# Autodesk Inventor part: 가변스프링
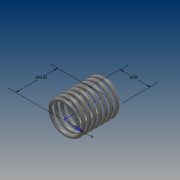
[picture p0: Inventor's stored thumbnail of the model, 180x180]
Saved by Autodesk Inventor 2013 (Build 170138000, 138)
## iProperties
Created: 2015-01
Part Number: 가변스프링
Material: 강철, 탄소
Document SubType Name: Modeling
Designer: Administrator
Density: 7.87 g/cm^3
Mass: 80.1301 g
Surface Area: 103.217 cm^2
Volume: 10.1817 cm^3
Author: Administrator
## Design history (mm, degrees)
sketch "스케치1"
  geometry: L1 (0, 0)-(17.5, 0); L2 (17.5, 0)-(17.5, 48.5); L3 (17.5, 48.5)-(0, 48.5); L4 (0, 48.5)-(0, 0); C1 r 2 at (17.5, 0)
  constraints: 8 end point, 2 parallel, 1 centre point, 1 coincident, 1 horizontal, 1 perpendicular
  dimensions: "d0" = 48.5 distance of L3.end L1.start (derived); "d1" = 35 diameter of L2 L4; "d2" = 4 diameter of C1
feature "코일1" pitch "d3" = 10; turns "d5" = 7.5; dims "d4" = 48.5 (= d0), "d6" = 0, angle "d7" = 90 deg, angle "d8" = 90 deg, "d9" = 0, "d10" = 0
node "작업 평면1"
sketch "스케치2"
  geometry: L1 (33, 0)-(37, 0) reference; 1 further point
  constraints: 1 horizontal alignment
extrude "돌출1" cut sketch "스케치2" stored distance "d12" = 10; taper "d13" = 0 deg
node "작업 평면2"
sketch "스케치3"
  geometry: L1 (15.5, 0)-(19.5, 0) reference; 1 further point
  constraints: 1 horizontal alignment
extrude "돌출2" cut sketch "스케치3" stored distance "d15" = 10; taper "d16" = 0 deg
node "솔리드1"
node "절단 모서리 투영1"
node "절단 모서리 투영2"
other parameters: "d11" = 90 deg, "d14" = 90 deg
